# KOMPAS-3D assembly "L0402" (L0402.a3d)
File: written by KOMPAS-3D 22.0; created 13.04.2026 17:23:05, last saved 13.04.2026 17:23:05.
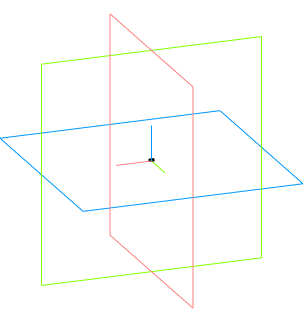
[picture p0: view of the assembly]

Document properties: Автор: Andrey; Полное имя файла: C:\Users\User1\Documents\L0402.a3d

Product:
- Component [assembly]: ASSEMBLY  | qty 1  | source file: ASSEMBLY_7.a3d
- Part/product: L0402
    Комментарий: L0402

Referenced files in C:\Users\User1\Documents\: ASSEMBLY_7.a3d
